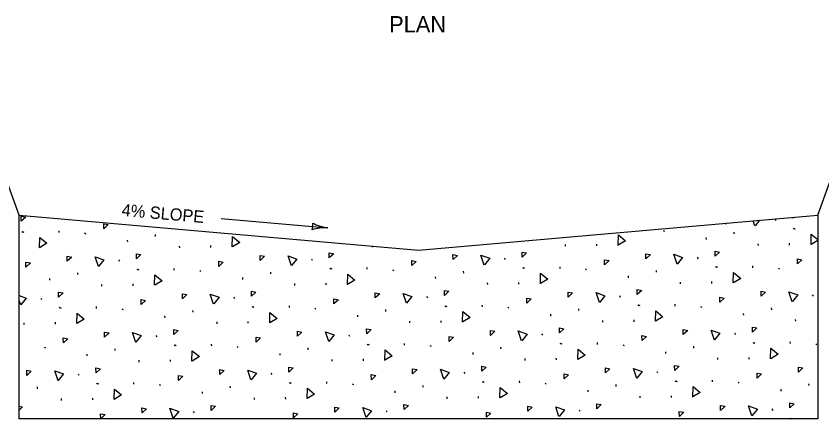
# Model space of a CAD drawing. Extents: x 49991.4 to 50021, y 49987.6 to 50011.4.
# Drawn here: x 50013.656 to 50017.61, y 50001.61 to 50003.587 of the extents above; entities that cross this region are included whole.
import ezdxf

# ---------------------------------------------------------------- set-up
doc = ezdxf.new("R2010")
doc.units = 0
for name, color, linetype in [('Level 1', 7, 'Continuous'), ('Level 2', 7, 'Continuous'), ('Level 3', 7, 'Continuous')]:
    doc.layers.add(name, color=color, linetype=linetype)

msp = doc.modelspace()

# ---------------------------------------------------------------- linework, layer by layer
at = {"layer": 'Level 1'}
for p, q in [((50013.6715, 50002.6101), (50013.6138, 50002.7686)), ((50017.5901, 50002.6101), (50017.6478, 50002.7686)), ((50013.6715, 50001.6101), (50013.6715, 50002.6101)), ((50013.6715, 50002.6101), (50015.6308, 50002.4387)), ((50015.6308, 50002.4387), (50017.5902, 50002.6101)), ((50017.3798, 50002.591), (50017.3841, 50002.5842)), ((50017.5902, 50002.6101), (50017.5902, 50001.6101)), ((50013.8678, 50002.5242), (50013.8674, 50002.5329)), ((50016.8319, 50002.534), (50016.8374, 50002.5308)), ((50017.4698, 50002.5454), (50017.4753, 50002.5421)), ((50017.4739, 50002.5451), (50017.4794, 50002.5419)), ((50013.6839, 50002.5297), (50013.6894, 50002.5265)), ((50013.6879, 50002.5295), (50013.6935, 50002.5263)), ((50013.9924, 50002.5223), (50013.998, 50002.519)), ((50014.3411, 50002.5059), (50014.3407, 50002.5147)), ((50017.0433, 50002.4907), (50017.043, 50002.4994)), ((50017.1805, 50002.5177), (50017.1802, 50002.5264)), ((50014.2039, 50002.4789), (50014.2035, 50002.4877)), ((50014.4591, 50002.4492), (50014.4587, 50002.458)), ((50014.6124, 50002.4514), (50014.6121, 50002.4602)), ((50015.4056, 50002.4531), (50015.4054, 50002.4584)), ((50016.352, 50002.4571), (50016.3517, 50002.4658)), ((50016.5054, 50002.4592), (50016.5051, 50002.468)), ((50017.2985, 50002.461), (50017.2982, 50002.4697)), ((50017.4519, 50002.4631), (50017.4515, 50002.4719)), ((50014.1587, 50002.3912), (50014.1631, 50002.3844)), ((50015.1052, 50002.3951), (50015.1095, 50002.3884)), ((50016.0517, 50002.399), (50016.056, 50002.3923)), ((50016.9982, 50002.403), (50017.0025, 50002.3962)), ((50014.2488, 50002.3456), (50014.2543, 50002.3424)), ((50014.2528, 50002.3454), (50014.2584, 50002.3422)), ((50014.4327, 50002.3401), (50014.4323, 50002.3488)), ((50014.5574, 50002.3382), (50014.5629, 50002.3349)), ((50015.1953, 50002.3495), (50015.2008, 50002.3463)), ((50015.1993, 50002.3493), (50015.2049, 50002.3461)), ((50015.3792, 50002.344), (50015.3788, 50002.3527)), ((50015.5038, 50002.3421), (50015.5094, 50002.3389)), ((50016.1417, 50002.3534), (50016.1473, 50002.3502)), ((50016.1458, 50002.3532), (50016.1514, 50002.35)), ((50016.3256, 50002.3479), (50016.3253, 50002.3566)), ((50016.4503, 50002.346), (50016.4559, 50002.3428)), ((50016.7989, 50002.3296), (50016.7986, 50002.3384)), ((50017.0882, 50002.3574), (50017.0938, 50002.3541)), ((50017.0923, 50002.3571), (50017.0978, 50002.3539)), ((50017.2721, 50002.3518), (50017.2718, 50002.3605)), ((50017.3968, 50002.3499), (50017.4024, 50002.3467)), ((50013.8223, 50002.2909), (50013.822, 50002.2997)), ((50013.9595, 50002.3179), (50013.9591, 50002.3267)), ((50014.7688, 50002.2948), (50014.7684, 50002.3036)), ((50014.906, 50002.3218), (50014.9056, 50002.3306)), ((50015.7153, 50002.2987), (50015.7149, 50002.3075)), ((50015.8525, 50002.3257), (50015.8521, 50002.3345)), ((50016.6618, 50002.3027), (50016.6614, 50002.3114)), ((50014.0775, 50002.2612), (50014.0772, 50002.27)), ((50014.2309, 50002.2634), (50014.2305, 50002.2722)), ((50015.024, 50002.2651), (50015.0236, 50002.2739)), ((50015.1773, 50002.2673), (50015.177, 50002.2761)), ((50015.9705, 50002.2691), (50015.9701, 50002.2778)), ((50016.1238, 50002.2712), (50016.1235, 50002.28)), ((50016.917, 50002.273), (50016.9166, 50002.2817)), ((50017.0703, 50002.2751), (50017.07, 50002.2839)), ((50017.5631, 50002.2189), (50017.5674, 50002.2121)), ((50013.7772, 50002.2032), (50013.7815, 50002.1964)), ((50014.7236, 50002.2071), (50014.728, 50002.2004)), ((50015.6701, 50002.211), (50015.6745, 50002.2043)), ((50016.6166, 50002.2149), (50016.6209, 50002.2082)), ((50013.8672, 50002.1576), (50013.8727, 50002.1544)), ((50013.8713, 50002.1574), (50013.8768, 50002.1542)), ((50014.0511, 50002.1521), (50014.0507, 50002.1608)), ((50014.1758, 50002.1502), (50014.1813, 50002.1469)), ((50014.5244, 50002.1338), (50014.524, 50002.1426)), ((50014.8137, 50002.1615), (50014.8192, 50002.1583)), ((50014.8178, 50002.1613), (50014.8233, 50002.1581)), ((50014.9976, 50002.156), (50014.9972, 50002.1647)), ((50015.1223, 50002.1541), (50015.1278, 50002.1509)), ((50015.4709, 50002.1377), (50015.4705, 50002.1465)), ((50015.7602, 50002.1654), (50015.7657, 50002.1622)), ((50015.7642, 50002.1652), (50015.7698, 50002.162)), ((50015.9441, 50002.1599), (50015.9437, 50002.1686)), ((50016.0688, 50002.158), (50016.0743, 50002.1548)), ((50016.4174, 50002.1416), (50016.417, 50002.1504)), ((50016.7066, 50002.1693), (50016.7122, 50002.1661)), ((50016.7107, 50002.1691), (50016.7163, 50002.1659)), ((50016.8905, 50002.1638), (50016.8902, 50002.1725)), ((50017.0152, 50002.1619), (50017.0208, 50002.1587)), ((50017.3638, 50002.1456), (50017.3635, 50002.1543)), ((50014.3872, 50002.1068), (50014.3869, 50002.1156)), ((50015.3337, 50002.1107), (50015.3334, 50002.1195)), ((50016.2802, 50002.1146), (50016.2798, 50002.1234)), ((50017.2267, 50002.1186), (50017.2263, 50002.1273)), ((50013.6959, 50002.0732), (50013.6956, 50002.082)), ((50013.8493, 50002.0754), (50013.8489, 50002.0841)), ((50014.6424, 50002.0771), (50014.6421, 50002.0859)), ((50014.7958, 50002.0793), (50014.7954, 50002.0881)), ((50015.5889, 50002.081), (50015.5885, 50002.0898)), ((50015.7423, 50002.0832), (50015.7419, 50002.092)), ((50016.5354, 50002.085), (50016.535, 50002.0937)), ((50016.6887, 50002.0871), (50016.6884, 50002.0959)), ((50017.4819, 50002.0889), (50017.4815, 50002.0976)), ((50014.3421, 50002.0191), (50014.3464, 50002.0123)), ((50015.2885, 50002.023), (50015.2929, 50002.0163)), ((50016.235, 50002.0269), (50016.2394, 50002.0202)), ((50017.1815, 50002.0309), (50017.1858, 50002.0241)), ((50015.5625, 50001.9719), (50015.5621, 50001.9806)), ((50016.3251, 50001.9813), (50016.3306, 50001.9781)), ((50016.3292, 50001.9811), (50016.3347, 50001.9779)), ((50016.509, 50001.9758), (50016.5086, 50001.9845)), ((50017.2716, 50001.9853), (50017.2771, 50001.982)), ((50017.2756, 50001.985), (50017.2812, 50001.9818)), ((50017.4555, 50001.9797), (50017.4551, 50001.9884)), ((50013.7942, 50001.9621), (50013.7998, 50001.9589)), ((50014.1428, 50001.9458), (50014.1425, 50001.9546)), ((50014.4321, 50001.9735), (50014.4376, 50001.9703)), ((50014.4362, 50001.9733), (50014.4417, 50001.9701)), ((50014.616, 50001.968), (50014.6157, 50001.9767)), ((50014.7407, 50001.9661), (50014.7462, 50001.9628)), ((50015.0893, 50001.9497), (50015.089, 50001.9585)), ((50015.3786, 50001.9774), (50015.3841, 50001.9742)), ((50015.3827, 50001.9772), (50015.3882, 50001.974)), ((50015.6872, 50001.97), (50015.6927, 50001.9668)), ((50016.0358, 50001.9536), (50016.0354, 50001.9624)), ((50016.6337, 50001.9739), (50016.6392, 50001.9707)), ((50016.9823, 50001.9575), (50016.9819, 50001.9663)), ((50017.5801, 50001.9778), (50017.5857, 50001.9746)), ((50014.0057, 50001.9188), (50014.0053, 50001.9276)), ((50014.9521, 50001.9227), (50014.9518, 50001.9315)), ((50015.2073, 50001.893), (50015.207, 50001.9018)), ((50015.3607, 50001.8952), (50015.3603, 50001.904)), ((50015.8986, 50001.9266), (50015.8983, 50001.9354)), ((50016.1538, 50001.897), (50016.1535, 50001.9057)), ((50016.3072, 50001.8991), (50016.3068, 50001.9079)), ((50016.8451, 50001.9306), (50016.8448, 50001.9393)), ((50017.1003, 50001.9009), (50017.0999, 50001.9096)), ((50017.2536, 50001.903), (50017.2533, 50001.9118)), ((50014.2608, 50001.8891), (50014.2605, 50001.8979)), ((50014.4142, 50001.8913), (50014.4138, 50001.9)), ((50013.9605, 50001.8311), (50013.9648, 50001.8243)), ((50014.907, 50001.835), (50014.9113, 50001.8283)), ((50015.8535, 50001.8389), (50015.8578, 50001.8322)), ((50016.7999, 50001.8428), (50016.8043, 50001.8361)), ((50014.0505, 50001.7855), (50014.0561, 50001.7823)), ((50014.0546, 50001.7853), (50014.0602, 50001.7821)), ((50014.2344, 50001.78), (50014.2341, 50001.7887)), ((50014.997, 50001.7894), (50015.0026, 50001.7862)), ((50015.0011, 50001.7892), (50015.0066, 50001.786)), ((50015.1809, 50001.7839), (50015.1806, 50001.7926)), ((50015.3056, 50001.782), (50015.3111, 50001.7788)), ((50015.9435, 50001.7933), (50015.949, 50001.7901)), ((50015.9476, 50001.7931), (50015.9531, 50001.7899)), ((50016.1274, 50001.7878), (50016.1271, 50001.7965)), ((50016.2521, 50001.7859), (50016.2576, 50001.7827)), ((50016.89, 50001.7972), (50016.8955, 50001.794)), ((50016.8941, 50001.797), (50016.8996, 50001.7938)), ((50017.0739, 50001.7917), (50017.0735, 50001.8004)), ((50017.1986, 50001.7898), (50017.2041, 50001.7866)), ((50017.5472, 50001.7735), (50017.5468, 50001.7822)), ((50013.7612, 50001.7578), (50013.7609, 50001.7666)), ((50014.3591, 50001.7781), (50014.3647, 50001.7748)), ((50014.5706, 50001.7347), (50014.5702, 50001.7435)), ((50014.7077, 50001.7617), (50014.7074, 50001.7705)), ((50015.517, 50001.7386), (50015.5167, 50001.7474)), ((50015.6542, 50001.7656), (50015.6539, 50001.7744)), ((50016.4635, 50001.7425), (50016.4632, 50001.7513)), ((50016.6007, 50001.7695), (50016.6004, 50001.7783)), ((50017.41, 50001.7465), (50017.4097, 50001.7552)), ((50013.8793, 50001.7011), (50013.8789, 50001.7099)), ((50014.0326, 50001.7033), (50014.0323, 50001.712)), ((50014.8257, 50001.705), (50014.8254, 50001.7138)), ((50014.9791, 50001.7072), (50014.9788, 50001.716)), ((50015.7722, 50001.7089), (50015.7719, 50001.7177)), ((50015.9256, 50001.7111), (50015.9252, 50001.7199)), ((50016.7187, 50001.7129), (50016.7184, 50001.7216)), ((50016.8721, 50001.715), (50016.8717, 50001.7238)), ((50014.5254, 50001.647), (50014.5297, 50001.6402)), ((50015.4719, 50001.6509), (50015.4762, 50001.6442)), ((50016.4184, 50001.6548), (50016.4227, 50001.6481)), ((50017.3649, 50001.6588), (50017.3692, 50001.652)), ((50017.5902, 50001.6101), (50013.6715, 50001.6101)), ((50016.6921, 50001.6101), (50016.692, 50001.6124)), ((50017.4549, 50001.6132), (50017.4601, 50001.6101)), ((50017.459, 50001.6129), (50017.4638, 50001.6101))]:
    msp.add_line(p, q, dxfattribs=at)
for points in [[(50013.6818, 50002.5802), (50013.6815, 50002.6048), (50013.7033, 50002.6007), (50013.6818, 50002.5802)], [(50017.2815, 50002.5572), (50017.2732, 50002.5824)], [(50017.3041, 50002.5851), (50017.2821, 50002.5578)], [(50017.4719, 50002.5997), (50017.4677, 50002.5958)], [(50017.4677, 50002.5958), (50017.4677, 50002.5994)], [(50014.0863, 50002.5428), (50014.086, 50002.5674), (50014.1079, 50002.5633), (50014.0863, 50002.5428)], [(50013.7708, 50002.4497), (50013.7723, 50002.5009), (50013.8075, 50002.4717), (50013.7716, 50002.4501)], [(50014.7173, 50002.4536), (50014.7188, 50002.5048), (50014.754, 50002.4756), (50014.7181, 50002.454)], [(50016.6103, 50002.4614), (50016.6118, 50002.5126), (50016.6469, 50002.4834), (50016.6111, 50002.4618)], [(50017.5568, 50002.4653), (50017.5582, 50002.5165), (50017.5902, 50002.49)], [(50017.5902, 50002.4855), (50017.5575, 50002.4657)], [(50014.2467, 50002.3961), (50014.2464, 50002.4207), (50014.2683, 50002.4166), (50014.2467, 50002.3961)], [(50015.1932, 50002.4), (50015.1929, 50002.4246), (50015.2147, 50002.4205), (50015.1932, 50002.4)], [(50015.8004, 50002.3917), (50015.8001, 50002.4163), (50015.8219, 50002.4122), (50015.8004, 50002.3917)], [(50016.1397, 50002.4039), (50016.1394, 50002.4285), (50016.1612, 50002.4244), (50016.1397, 50002.4039)], [(50016.7468, 50002.3956), (50016.7466, 50002.4202), (50016.7684, 50002.4161), (50016.7468, 50002.3956)], [(50016.8999, 50002.3692), (50016.8838, 50002.4178), (50016.9268, 50002.4024), (50016.9005, 50002.3698)], [(50017.0861, 50002.4078), (50017.0859, 50002.4324), (50017.1077, 50002.4283), (50017.0861, 50002.4078)], [(50013.7047, 50002.3547), (50013.7045, 50002.3794), (50013.7263, 50002.3753), (50013.7047, 50002.3547)], [(50013.9074, 50002.3838), (50013.9071, 50002.4085), (50013.929, 50002.4044), (50013.9074, 50002.3838)], [(50014.0605, 50002.3574), (50014.0443, 50002.4061), (50014.0874, 50002.3907), (50014.0611, 50002.3581)], [(50014.6512, 50002.3587), (50014.651, 50002.3833), (50014.6728, 50002.3792), (50014.6512, 50002.3587)], [(50014.8539, 50002.3878), (50014.8536, 50002.4124), (50014.8754, 50002.4083), (50014.8539, 50002.3878)], [(50015.0069, 50002.3613), (50014.9908, 50002.41), (50015.0339, 50002.3946), (50015.0076, 50002.362)], [(50015.5977, 50002.3626), (50015.5974, 50002.3872), (50015.6193, 50002.3831), (50015.5977, 50002.3626)], [(50015.9534, 50002.3652), (50015.9373, 50002.4139), (50015.9803, 50002.3985), (50015.954, 50002.3659)], [(50016.5442, 50002.3665), (50016.5439, 50002.3911), (50016.5657, 50002.387), (50016.5442, 50002.3665)], [(50017.4907, 50002.3704), (50017.4904, 50002.395), (50017.5122, 50002.3909), (50017.4907, 50002.3704)], [(50014.3357, 50002.2656), (50014.3372, 50002.3168), (50014.3724, 50002.2876), (50014.3365, 50002.266)], [(50015.2822, 50002.2695), (50015.2837, 50002.3207), (50015.3189, 50002.2915), (50015.283, 50002.2699)], [(50016.2287, 50002.2734), (50016.2302, 50002.3246), (50016.2654, 50002.2954), (50016.2295, 50002.2738)], [(50017.1752, 50002.2773), (50017.1767, 50002.3285), (50017.2118, 50002.2993), (50017.176, 50002.2777)], [(50013.8651, 50002.2081), (50013.8649, 50002.2327), (50013.8867, 50002.2286), (50013.8651, 50002.2081)], [(50014.4723, 50002.1997), (50014.4721, 50002.2244), (50014.4939, 50002.2203), (50014.4723, 50002.1997)], [(50014.6254, 50002.1733), (50014.6092, 50002.222), (50014.6523, 50002.2066), (50014.626, 50002.174)], [(50014.8116, 50002.212), (50014.8113, 50002.2366), (50014.8332, 50002.2325), (50014.8116, 50002.212)], [(50015.4188, 50002.2037), (50015.4185, 50002.2283), (50015.4404, 50002.2242), (50015.4188, 50002.2037)], [(50015.5718, 50002.1772), (50015.5557, 50002.2259), (50015.5988, 50002.2105), (50015.5725, 50002.1779)], [(50015.7581, 50002.2159), (50015.7578, 50002.2405), (50015.7796, 50002.2364), (50015.7581, 50002.2159)], [(50016.3653, 50002.2076), (50016.365, 50002.2322), (50016.3868, 50002.2281), (50016.3653, 50002.2076)], [(50016.5183, 50002.1812), (50016.5022, 50002.2298), (50016.5453, 50002.2144), (50016.5189, 50002.1818)], [(50016.7046, 50002.2198), (50016.7043, 50002.2444), (50016.7261, 50002.2403), (50016.7046, 50002.2198)], [(50017.3118, 50002.2115), (50017.3115, 50002.2361), (50017.3333, 50002.232), (50017.3118, 50002.2115)], [(50017.4648, 50002.1851), (50017.4487, 50002.2337), (50017.4917, 50002.2183), (50017.4654, 50002.1857)], [(50013.6715, 50002.215), (50013.7058, 50002.2027), (50013.6795, 50002.1701)], [(50013.6789, 50002.1694), (50013.6715, 50002.1918)], [(50014.2696, 50002.1707), (50014.2694, 50002.1953), (50014.2912, 50002.1912), (50014.2696, 50002.1707)], [(50015.2161, 50002.1746), (50015.2159, 50002.1992), (50015.2377, 50002.1951), (50015.2161, 50002.1746)], [(50016.1626, 50002.1785), (50016.1623, 50002.2031), (50016.1842, 50002.199), (50016.1626, 50002.1785)], [(50017.1091, 50002.1824), (50017.1088, 50002.207), (50017.1306, 50002.2029), (50017.1091, 50002.1824)], [(50016.7936, 50002.0893), (50016.7951, 50002.1405), (50016.8303, 50002.1113), (50016.7944, 50002.0897)], [(50013.9542, 50002.0776), (50013.9556, 50002.1288), (50013.9908, 50002.0996), (50013.955, 50002.078)], [(50014.9006, 50002.0815), (50014.9021, 50002.1327), (50014.9373, 50002.1035), (50014.9014, 50002.0819)], [(50015.8471, 50002.0854), (50015.8486, 50002.1366), (50015.8838, 50002.1074), (50015.8479, 50002.0858)], [(50017.2695, 50002.0357), (50017.2692, 50002.0603), (50017.291, 50002.0562), (50017.2695, 50002.0357)], [(50014.0907, 50002.0117), (50014.0905, 50002.0364), (50014.1123, 50002.0323), (50014.0907, 50002.0117)], [(50014.2438, 50001.9853), (50014.2277, 50002.034), (50014.2707, 50002.0186), (50014.2444, 50001.986)], [(50014.43, 50002.024), (50014.4298, 50002.0486), (50014.4516, 50002.0445), (50014.43, 50002.024)], [(50015.0372, 50002.0157), (50015.037, 50002.0403), (50015.0588, 50002.0362), (50015.0372, 50002.0157)], [(50015.1903, 50001.9892), (50015.1742, 50002.0379), (50015.2172, 50002.0225), (50015.1909, 50001.9899)], [(50015.3765, 50002.0279), (50015.3763, 50002.0525), (50015.3981, 50002.0484), (50015.3765, 50002.0279)], [(50015.9837, 50002.0196), (50015.9834, 50002.0442), (50016.0053, 50002.0401), (50015.9837, 50002.0196)], [(50016.1368, 50001.9931), (50016.1206, 50002.0418), (50016.1637, 50002.0264), (50016.1374, 50001.9938)], [(50016.323, 50002.0318), (50016.3227, 50002.0564), (50016.3446, 50002.0523), (50016.323, 50002.0318)], [(50016.7275, 50001.9944), (50016.7273, 50002.019), (50016.7491, 50002.0149), (50016.7275, 50001.9944)], [(50016.9302, 50002.0235), (50016.9299, 50002.0481), (50016.9518, 50002.044), (50016.9302, 50002.0235)], [(50017.0832, 50001.9971), (50017.0671, 50002.0457), (50017.1102, 50002.0303), (50017.0839, 50001.9977)], [(50013.8881, 50001.9826), (50013.8878, 50002.0073), (50013.9096, 50002.0032), (50013.8881, 50001.9826)], [(50014.8345, 50001.9866), (50014.8343, 50002.0112), (50014.8561, 50002.0071), (50014.8345, 50001.9866)], [(50015.781, 50001.9905), (50015.7808, 50002.0151), (50015.8026, 50002.011), (50015.781, 50001.9905)], [(50014.5191, 50001.8935), (50014.5206, 50001.9447), (50014.5557, 50001.9155), (50014.5199, 50001.8939)], [(50015.4656, 50001.8974), (50015.467, 50001.9486), (50015.5022, 50001.9194), (50015.4663, 50001.8978)], [(50016.412, 50001.9013), (50016.4135, 50001.9525), (50016.4487, 50001.9233), (50016.4128, 50001.9017)], [(50017.3585, 50001.9052), (50017.36, 50001.9564), (50017.3952, 50001.9272), (50017.3593, 50001.9056)], [(50014.0485, 50001.836), (50014.0482, 50001.8606), (50014.07, 50001.8565), (50014.0485, 50001.836)], [(50014.9949, 50001.8399), (50014.9947, 50001.8645), (50015.0165, 50001.8604), (50014.9949, 50001.8399)], [(50015.9414, 50001.8438), (50015.9412, 50001.8684), (50015.963, 50001.8643), (50015.9414, 50001.8438)], [(50016.8879, 50001.8477), (50016.8877, 50001.8723), (50016.9095, 50001.8682), (50016.8879, 50001.8477)], [(50017.4951, 50001.8394), (50017.4948, 50001.864), (50017.5167, 50001.8599), (50017.4951, 50001.8394)], [(50013.7092, 50001.8237), (50013.7089, 50001.8484), (50013.7307, 50001.8443), (50013.7092, 50001.8237)], [(50013.8622, 50001.7973), (50013.8461, 50001.846), (50013.8891, 50001.8306), (50013.8628, 50001.798)], [(50014.453, 50001.7986), (50014.4527, 50001.8232), (50014.4745, 50001.8191), (50014.453, 50001.7986)], [(50014.6556, 50001.8276), (50014.6554, 50001.8523), (50014.6772, 50001.8482), (50014.6556, 50001.8276)], [(50014.8087, 50001.8012), (50014.7926, 50001.8499), (50014.8356, 50001.8345), (50014.8093, 50001.8019)], [(50015.3995, 50001.8025), (50015.3992, 50001.8271), (50015.421, 50001.823), (50015.3995, 50001.8025)], [(50015.6021, 50001.8316), (50015.6019, 50001.8562), (50015.6237, 50001.8521), (50015.6021, 50001.8316)], [(50015.7552, 50001.8051), (50015.7391, 50001.8538), (50015.7821, 50001.8384), (50015.7558, 50001.8058)], [(50016.3459, 50001.8064), (50016.3457, 50001.831), (50016.3675, 50001.8269), (50016.3459, 50001.8064)], [(50016.5486, 50001.8355), (50016.5484, 50001.8601), (50016.5702, 50001.856), (50016.5486, 50001.8355)], [(50016.7017, 50001.8091), (50016.6856, 50001.8577), (50016.7286, 50001.8423), (50016.7023, 50001.8097)], [(50017.2924, 50001.8103), (50017.2922, 50001.8349), (50017.314, 50001.8308), (50017.2924, 50001.8103)], [(50014.1375, 50001.7055), (50014.139, 50001.7567), (50014.1742, 50001.7275), (50014.1383, 50001.7059)], [(50015.084, 50001.7094), (50015.0855, 50001.7606), (50015.1206, 50001.7314), (50015.0848, 50001.7098)], [(50016.0305, 50001.7133), (50016.032, 50001.7645), (50016.0671, 50001.7353), (50016.0313, 50001.7137)], [(50016.9769, 50001.7172), (50016.9784, 50001.7684), (50017.0136, 50001.7392), (50016.9777, 50001.7176)], [(50013.6715, 50001.6717), (50013.6884, 50001.6685), (50013.6715, 50001.6524)], [(50014.2741, 50001.6396), (50014.2738, 50001.6643), (50014.2956, 50001.6602), (50014.2741, 50001.6396)], [(50014.6134, 50001.6519), (50014.6131, 50001.6765), (50014.6349, 50001.6724), (50014.6134, 50001.6519)], [(50015.2206, 50001.6436), (50015.2203, 50001.6682), (50015.2421, 50001.6641), (50015.2206, 50001.6436)], [(50015.3736, 50001.6171), (50015.3575, 50001.6658), (50015.4005, 50001.6504), (50015.3742, 50001.6178)], [(50015.5599, 50001.6558), (50015.5596, 50001.6804), (50015.5814, 50001.6763), (50015.5599, 50001.6558)], [(50016.167, 50001.6475), (50016.1668, 50001.6721), (50016.1886, 50001.668), (50016.167, 50001.6475)], [(50016.3201, 50001.621), (50016.304, 50001.6697), (50016.347, 50001.6543), (50016.3207, 50001.6217)], [(50016.5063, 50001.6597), (50016.5061, 50001.6843), (50016.5279, 50001.6802), (50016.5063, 50001.6597)], [(50017.1135, 50001.6514), (50017.1133, 50001.676), (50017.1351, 50001.6719), (50017.1135, 50001.6514)], [(50017.2666, 50001.625), (50017.2505, 50001.6736), (50017.2935, 50001.6582), (50017.2672, 50001.6256)], [(50017.4528, 50001.6636), (50017.4526, 50001.6882), (50017.4744, 50001.6841), (50017.4528, 50001.6636)], [(50014.0714, 50001.6105), (50014.0711, 50001.6352), (50014.093, 50001.6311), (50014.0714, 50001.6105)], [(50014.4271, 50001.6132), (50014.411, 50001.6619), (50014.4541, 50001.6465), (50014.4277, 50001.6139)], [(50015.0179, 50001.6145), (50015.0176, 50001.6391), (50015.0394, 50001.635), (50015.0179, 50001.6145)], [(50015.9644, 50001.6184), (50015.9641, 50001.643), (50015.9859, 50001.6389), (50015.9644, 50001.6184)], [(50016.9108, 50001.6223), (50016.9106, 50001.6469), (50016.9324, 50001.6428), (50016.9108, 50001.6223)]]:
    msp.add_lwpolyline(points, dxfattribs=at)
msp.add_arc((50017.1381, 50002.5717), 0.00363, 204.0261, 345.9724, dxfattribs=at)
at = {"layer": 'Level 3'}
msp.add_line((50014.6621, 50002.5937), (50015.1859, 50002.5479), dxfattribs=at)
for centre, radius, start, end in [((50015.0581, 50002.5591), 0.0548, 337.1347, 12.857), ((50015.177, 50002.3151), 0.233, 87.8232, 107.073), ((50015.2144, 50002.7684), 0.2223, 242.4519, 262.6354)]:
    msp.add_arc(centre, radius, start, end, dxfattribs=at)

# ---------------------------------------------------------------- texts
at = {"layer": 'Level 2'}
msp.add_text('PLAN', height=0.08, dxfattribs=at).set_placement((50015.4868, 50003.5066))
msp.add_text('4% SLOPE', height=0.06, rotation=355, dxfattribs=at).set_placement((50014.1725, 50002.6064))

doc.saveas('drawing.dxf')
